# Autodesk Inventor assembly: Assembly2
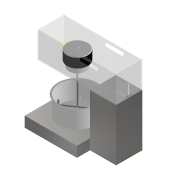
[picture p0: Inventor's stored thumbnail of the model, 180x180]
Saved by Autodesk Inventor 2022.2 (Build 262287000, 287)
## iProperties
Created: 2022-03
Part Number: Assembly2
Document SubType Name: Assembly
Designer: OHIL G H
Author: OHIL G H
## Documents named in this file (9)
- D:\BME inventor\mixing machine\New folder\Assembly2.iam
- D:\BME inventor\mixing machine\New folder\side.ipt
- D:\BME inventor\mixing machine\New folder\hinge.ipt
- D:\BME inventor\mixing machine\New folder\top.ipt
- D:\BME inventor\mixing machine\New folder\motor.ipt
- D:\BME inventor\mixing machine\base.ipt
- D:\BME inventor\mixing machine\New folder\clamp.ipt
- D:\BME inventor\mixing machine\New folder\container.ipt
- D:\BME inventor\mixing machine\blades.ipt
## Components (8 placed, 8 different names)
1. side:1 — Mate:1, Flush:1, Mate:2, Flush:2, Mate:3, Mate:4, Mate:7, Mate:8, Mate:9
2. hinge:1 — Mate:1, Flush:1, Mate:2
3. top:2 — Flush:2, Mate:3, Mate:4, Mate:10, Mate:11, Mate:13
4. base:1 — Mate:7, Mate:8, Mate:9, Mate:18
5. motor:1 — Mate:10, Mate:11, Mate:12
6. clamp:1 — Mate:12, Mate:13, Mate:16, Mate:17
7. blades:1 — Mate:16
8. container:1 — Mate:17, Mate:18
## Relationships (16: Mate 14, Flush 2)
- Mate:1: side:1 ↔ hinge:1
- Flush:1: side:1 ↔ hinge:1
- Mate:2: side:1 ↔ hinge:1
- Flush:2: side:1 ↔ top:2
- Mate:3: side:1 ↔ top:2
- Mate:4: side:1 ↔ top:2
- Mate:7: side:1 ↔ base:1
- Mate:8: side:1 ↔ base:1
- Mate:9: side:1 ↔ base:1
- Mate:10: top:2 ↔ motor:1
- Mate:11: top:2 ↔ motor:1
- Mate:12: motor:1 ↔ clamp:1
- Mate:13: top:2 ↔ clamp:1
- Mate:16: clamp:1 ↔ blades:1
- Mate:17: clamp:1 ↔ container:1
- Mate:18: base:1 ↔ container:1
